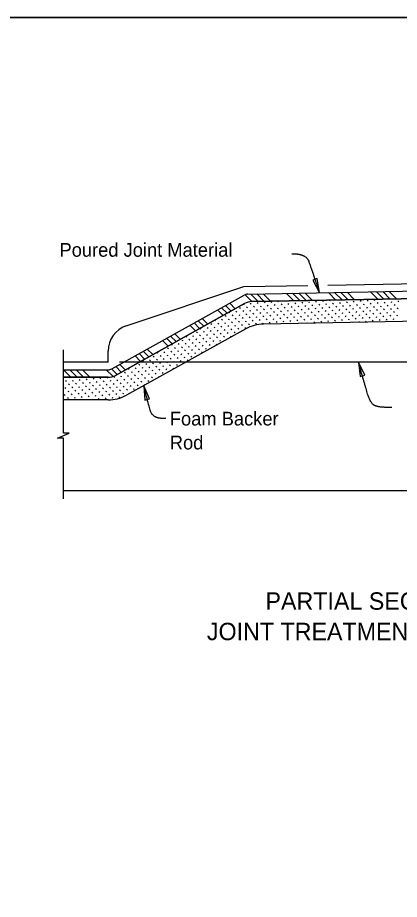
# Model space of a CAD drawing. Extents: x 0 to 15.4, y 0 to 9.7.
# Drawn here: x 5 to 7.109, y 4.865 to 9.73 of the extents above; entities that cross this region are included whole.
import ezdxf

# ---------------------------------------------------------------- set-up
doc = ezdxf.new("R2010")
doc.units = 0
for name, color, linetype in [('Dimension', 7, 'Continuous'), ('Miscellaneous', 7, 'Continuous'), ('Miscellaneous1', 7, 'Continuous'), ('SupstrConc', 7, 'Continuous'), ('SupstrConc_h', 7, 'Continuous'), ('TextStructures', 7, 'Continuous')]:
    doc.layers.add(name, color=color, linetype=linetype)

msp = doc.modelspace()

# ---------------------------------------------------------------- linework, layer by layer
at = {"layer": 'Dimension'}
for points in [[(6.6664, 8.2115), (6.6546, 8.2899), (6.6295, 8.2816)], [(6.8826, 7.8283), (6.8914, 7.7495), (6.9169, 7.7568)], [(5.6962, 7.6983), (5.7024, 7.6193), (5.7281, 7.6258)]]:
    msp.add_lwpolyline(points, close=True, dxfattribs=at)
msp.add_lwpolyline([(5.2525, 7.0744), (5.2525, 7.4095), (5.2194, 7.4095), (5.2834, 7.4378), (5.2525, 7.4378), (5.2525, 7.8962)], dxfattribs=at)
for points in [[(6.5146, 8.4272), (6.5542, 8.4272), (6.5971, 8.4085), (6.6125, 8.3755), (6.6664, 8.2115)], [(7.0668, 7.579), (6.995, 7.578), (6.9478, 7.6016), (6.9138, 7.7197), (6.8826, 7.8283)], [(5.8183, 7.5178), (5.7787, 7.5178), (5.7501, 7.5321), (5.7325, 7.5541), (5.6962, 7.6983)]]:
    msp.add_open_spline(points, degree=2, dxfattribs=at)
at = {"layer": 'Miscellaneous'}
for p, q in [((6.2709, 8.2042), (7.6932, 8.2305)), ((5.5197, 7.7924), (6.2514, 8.1989)), ((6.2563, 8.2002), (6.2936, 8.1629)), ((6.287, 8.2045), (6.328, 8.1635)), ((7.6925, 8.1888), (6.2925, 8.1629)), ((6.2925, 8.1629), (7.6925, 8.1888)), ((6.3214, 8.2051), (6.3623, 8.1642)), ((6.3558, 8.2058), (6.3967, 8.1648)), ((6.4845, 8.2081), (6.5255, 8.1672)), ((6.5189, 8.2088), (6.5598, 8.1678)), ((6.5532, 8.2094), (6.5942, 8.1685)), ((6.5876, 8.2101), (6.6285, 8.1691)), ((6.7164, 8.2124), (6.7573, 8.1715)), ((6.7507, 8.2131), (6.7917, 8.1721)), ((6.7851, 8.2137), (6.826, 8.1728)), ((6.8194, 8.2144), (6.8604, 8.1734)), ((6.9482, 8.2167), (6.9892, 8.1758)), ((6.9703, 8.1691), (6.9736, 8.1747)), ((6.9826, 8.2174), (7.0235, 8.1764)), ((7.0085, 8.1724), (7.0107, 8.1762)), ((7.0169, 8.218), (7.0579, 8.1771)), ((7.0467, 8.1756), (7.0474, 8.1769)), ((7.0513, 8.2186), (7.0922, 8.1777)), ((6.2535, 8.1524), (5.5399, 7.7559)), ((5.5399, 7.7559), (6.2535, 8.1524)), ((6.1261, 8.1293), (6.1567, 8.0986)), ((6.1486, 8.1418), (6.1792, 8.1111)), ((6.1711, 8.1543), (6.2017, 8.1236)), ((6.228, 8.125), (6.2312, 8.1306)), ((6.2487, 8.1457), (6.2519, 8.1513)), ((6.2661, 8.1283), (6.2694, 8.1339)), ((6.2868, 8.149), (6.2901, 8.1546)), ((6.3043, 8.1315), (6.3075, 8.1371)), ((6.325, 8.1522), (6.3282, 8.1578)), ((6.3424, 8.1347), (6.3457, 8.1403)), ((6.3631, 8.1554), (6.3664, 8.161)), ((6.3806, 8.138), (6.3838, 8.1436)), ((6.398, 8.1205), (6.4013, 8.1261)), ((6.4013, 8.1587), (6.4045, 8.1643)), ((6.4187, 8.1412), (6.422, 8.1468)), ((6.4362, 8.1238), (6.4394, 8.1294)), ((6.4394, 8.1619), (6.4416, 8.1656)), ((6.4569, 8.1445), (6.4601, 8.1501)), ((6.4743, 8.127), (6.4776, 8.1326)), ((6.4776, 8.1652), (6.4783, 8.1663)), ((6.495, 8.1477), (6.4983, 8.1533)), ((6.5125, 8.1303), (6.5157, 8.1359)), ((6.5332, 8.151), (6.5364, 8.1565)), ((6.5507, 8.1335), (6.5539, 8.1391)), ((6.5713, 8.1542), (6.5746, 8.1598)), ((6.5888, 8.1367), (6.592, 8.1423)), ((6.6063, 8.1193), (6.6095, 8.1249)), ((6.6095, 8.1574), (6.6127, 8.163)), ((6.627, 8.14), (6.6302, 8.1456)), ((6.6444, 8.1225), (6.6477, 8.1281)), ((6.6477, 8.1607), (6.6509, 8.1663)), ((6.6651, 8.1432), (6.6684, 8.1488)), ((6.6826, 8.1258), (6.6858, 8.1314)), ((6.6858, 8.1639), (6.6891, 8.1695)), ((6.7033, 8.1465), (6.7065, 8.1521)), ((6.7207, 8.129), (6.724, 8.1346)), ((6.724, 8.1672), (6.7261, 8.1709)), ((6.7414, 8.1497), (6.7447, 8.1553)), ((6.7589, 8.1322), (6.7621, 8.1378)), ((6.7621, 8.1704), (6.7628, 8.1716)), ((6.7796, 8.1529), (6.7828, 8.1585)), ((6.797, 8.1355), (6.8003, 8.1411)), ((6.8177, 8.1562), (6.821, 8.1618)), ((6.8352, 8.1387), (6.8384, 8.1443)), ((6.8526, 8.1213), (6.8559, 8.1269)), ((6.8559, 8.1594), (6.8591, 8.165)), ((6.8733, 8.142), (6.8766, 8.1476)), ((6.8908, 8.1245), (6.894, 8.1301)), ((6.894, 8.1627), (6.8973, 8.1683)), ((6.9115, 8.1452), (6.9147, 8.1508)), ((6.929, 8.1277), (6.9322, 8.1333)), ((6.9322, 8.1659), (6.9354, 8.1715)), ((6.9497, 8.1484), (6.9529, 8.154)), ((6.9671, 8.131), (6.9703, 8.1366)), ((6.9878, 8.1517), (6.991, 8.1573)), ((7.0053, 8.1342), (7.0085, 8.1398)), ((7.026, 8.1549), (7.0292, 8.1605)), ((7.0434, 8.1375), (7.0467, 8.1431)), ((7.0609, 8.12), (7.0641, 8.1256)), ((7.0641, 8.1582), (7.0674, 8.1638)), ((7.0816, 8.1407), (7.0848, 8.1463)), ((7.099, 8.1233), (7.1023, 8.1289)), ((7.1023, 8.1614), (7.1055, 8.167)), ((6.1036, 8.1168), (6.1342, 8.0861)), ((6.1484, 8.0804), (6.1517, 8.086)), ((6.1691, 8.1011), (6.1723, 8.1067)), ((6.1866, 8.0836), (6.1898, 8.0892)), ((6.2073, 8.1043), (6.2105, 8.1099)), ((6.2247, 8.0869), (6.228, 8.0925)), ((6.2454, 8.1076), (6.2487, 8.1132)), ((6.2629, 8.0901), (6.2661, 8.0957)), ((6.2803, 8.0727), (6.2836, 8.0783)), ((6.2836, 8.1108), (6.2868, 8.1164)), ((6.301, 8.0934), (6.3043, 8.099)), ((6.3185, 8.0759), (6.3217, 8.0815)), ((6.3217, 8.114), (6.325, 8.1196)), ((6.3392, 8.0966), (6.3424, 8.1022)), ((6.3566, 8.0791), (6.3599, 8.0847)), ((6.3599, 8.1173), (6.3631, 8.1229)), ((6.3773, 8.0998), (6.3806, 8.1054)), ((6.3948, 8.0824), (6.398, 8.088)), ((6.4155, 8.1031), (6.4187, 8.1087)), ((6.4329, 8.0856), (6.4362, 8.0912)), ((6.4536, 8.1063), (6.4569, 8.1119)), ((6.4711, 8.0889), (6.4743, 8.0945)), ((6.4886, 8.0714), (6.4918, 8.077)), ((6.4918, 8.1096), (6.495, 8.1152)), ((6.5093, 8.0921), (6.5125, 8.0977)), ((6.5267, 8.0746), (6.53, 8.0802)), ((6.53, 8.1128), (6.5332, 8.1184)), ((6.5474, 8.0953), (6.5507, 8.1009)), ((6.5649, 8.0779), (6.5681, 8.0835)), ((6.5681, 8.116), (6.5713, 8.1216)), ((6.5856, 8.0986), (6.5888, 8.1042)), ((6.603, 8.0811), (6.6063, 8.0867)), ((6.6237, 8.1018), (6.627, 8.1074)), ((6.6412, 8.0844), (6.6444, 8.09)), ((6.6619, 8.1051), (6.6651, 8.1107)), ((6.6793, 8.0876), (6.6826, 8.0932)), ((6.6968, 8.0702), (6.7, 8.0757)), ((6.7, 8.1083), (6.7033, 8.1139)), ((6.7175, 8.0908), (6.7207, 8.0964)), ((6.7349, 8.0734), (6.7382, 8.079)), ((6.7382, 8.1115), (6.7414, 8.1171)), ((6.7556, 8.0941), (6.7589, 8.0997)), ((6.7731, 8.0766), (6.7763, 8.0822)), ((6.7763, 8.1148), (6.7796, 8.1204)), ((6.7938, 8.0973), (6.797, 8.1029)), ((6.8112, 8.0799), (6.8145, 8.0855)), ((6.8145, 8.118), (6.8177, 8.1236)), ((6.8319, 8.1006), (6.8352, 8.1062)), ((6.8494, 8.0831), (6.8526, 8.0887)), ((6.8701, 8.1038), (6.8733, 8.1094)), ((6.8876, 8.0864), (6.8908, 8.092)), ((6.9083, 8.1071), (6.9115, 8.1127)), ((6.9257, 8.0896), (6.929, 8.0952)), ((6.9432, 8.0721), (6.9464, 8.0777)), ((6.9464, 8.1103), (6.9497, 8.1159)), ((6.9639, 8.0928), (6.9671, 8.0984)), ((6.9813, 8.0754), (6.9846, 8.081)), ((6.9846, 8.1135), (6.9878, 8.1191)), ((7.002, 8.0961), (7.0053, 8.1017)), ((7.0195, 8.0786), (7.0227, 8.0842)), ((7.0227, 8.1168), (7.026, 8.1224)), ((7.0402, 8.0993), (7.0434, 8.1049)), ((7.0576, 8.0819), (7.0609, 8.0875)), ((7.0783, 8.1026), (7.0816, 8.1082)), ((7.0958, 8.0851), (7.099, 8.0907)), ((5.9518, 8.0325), (5.9824, 8.0018)), ((5.9743, 8.045), (6.0049, 8.0143)), ((5.9968, 8.0575), (6.0274, 8.0268)), ((6.0193, 8.07), (6.0499, 8.0393)), ((6.0689, 8.0358), (6.0721, 8.0414)), ((6.0896, 8.0565), (6.0928, 8.062)), ((6.107, 8.039), (6.1103, 8.0446)), ((6.1245, 8.0215), (6.1277, 8.0271)), ((6.1277, 8.0597), (6.131, 8.0653)), ((6.1452, 8.0422), (6.1484, 8.0478)), ((6.1626, 8.0248), (6.1659, 8.0304)), ((6.1659, 8.0629), (6.1691, 8.0685)), ((6.1833, 8.0455), (6.1866, 8.0511)), ((6.2008, 8.028), (6.204, 8.0336)), ((6.204, 8.0662), (6.2073, 8.0718)), ((6.2215, 8.0487), (6.2247, 8.0543)), ((6.2389, 8.0313), (6.2422, 8.0369)), ((6.2422, 8.0694), (6.2454, 8.075)), ((6.2596, 8.052), (6.2629, 8.0576)), ((6.2771, 8.0345), (6.2803, 8.0401)), ((6.2978, 8.0552), (6.301, 8.0608)), ((6.3152, 8.0377), (6.3185, 8.0433)), ((6.3359, 8.0584), (6.3392, 8.064)), ((6.3534, 8.041), (6.3566, 8.0466)), ((7.6901, 8.0638), (6.3571, 8.0391)), ((6.3741, 8.0617), (6.3773, 8.0673)), ((6.3916, 8.0442), (6.3948, 8.0498)), ((6.4122, 8.0649), (6.4155, 8.0705)), ((6.4297, 8.0475), (6.4329, 8.0531)), ((6.4504, 8.0682), (6.4536, 8.0738)), ((6.4679, 8.0507), (6.4711, 8.0563)), ((6.506, 8.0539), (6.5093, 8.0595)), ((6.5442, 8.0572), (6.5474, 8.0628)), ((6.5635, 8.0429), (6.5649, 8.0453)), ((6.5823, 8.0604), (6.5856, 8.066)), ((6.6001, 8.0436), (6.603, 8.0486)), ((6.6205, 8.0637), (6.6237, 8.0693)), ((6.6379, 8.0462), (6.6412, 8.0518)), ((6.6586, 8.0669), (6.6619, 8.0725)), ((6.6761, 8.0495), (6.6793, 8.0551)), ((6.7142, 8.0527), (6.7175, 8.0583)), ((6.7524, 8.0559), (6.7556, 8.0615)), ((6.7906, 8.0592), (6.7938, 8.0648)), ((6.8287, 8.0624), (6.8319, 8.068)), ((6.848, 8.0482), (6.8494, 8.0506)), ((6.8669, 8.0657), (6.8701, 8.0713)), ((6.8847, 8.0488), (6.8876, 8.0538)), ((6.905, 8.0689), (6.9083, 8.0745)), ((6.9225, 8.0514), (6.9257, 8.057)), ((6.9606, 8.0547), (6.9639, 8.0603)), ((6.9988, 8.0579), (7.002, 8.0635)), ((7.0369, 8.0612), (7.0402, 8.0668)), ((7.0751, 8.0644), (7.0783, 8.07)), ((6.2598, 8.0129), (5.6006, 7.6466)), ((5.8675, 7.9856), (5.8981, 7.9549)), ((5.9893, 7.9911), (5.9926, 7.9967)), ((6.0068, 7.9737), (6.01, 7.9793)), ((6.01, 8.0118), (6.0133, 8.0174)), ((6.0275, 7.9944), (6.0307, 8)), ((6.0449, 7.9769), (6.0482, 7.9825)), ((6.0482, 8.0151), (6.0514, 8.0207)), ((6.0656, 7.9976), (6.0689, 8.0032)), ((6.0831, 7.9801), (6.0863, 7.9857)), ((6.0863, 8.0183), (6.0896, 8.0239)), ((6.1038, 8.0008), (6.107, 8.0064)), ((6.1212, 7.9834), (6.1245, 7.989)), ((6.1419, 8.0041), (6.1452, 8.0097)), ((6.1594, 7.9866), (6.1626, 7.9922)), ((6.1801, 8.0073), (6.1833, 8.0129)), ((6.1975, 7.9899), (6.2008, 7.9955)), ((6.2182, 8.0106), (6.2215, 8.0162)), ((6.2564, 8.0138), (6.2596, 8.0194)), ((5.8, 7.9481), (5.8306, 7.9174)), ((5.8225, 7.9606), (5.8531, 7.9299)), ((5.845, 7.9731), (5.8756, 7.9424)), ((5.8891, 7.9258), (5.8923, 7.9314)), ((5.9098, 7.9465), (5.913, 7.9521)), ((5.9272, 7.929), (5.9305, 7.9346)), ((5.9305, 7.9672), (5.9337, 7.9728)), ((5.9479, 7.9497), (5.9512, 7.9553)), ((5.9654, 7.9323), (5.9686, 7.9379)), ((5.9686, 7.9704), (5.9719, 7.976)), ((5.9861, 7.953), (5.9893, 7.9586)), ((6.0035, 7.9355), (6.0068, 7.9411)), ((6.0242, 7.9562), (6.0275, 7.9618)), ((6.0417, 7.9387), (6.0449, 7.9443)), ((6.0624, 7.9594), (6.0656, 7.965)), ((6.0798, 7.942), (6.0831, 7.9476)), ((6.0973, 7.9245), (6.1005, 7.9301)), ((6.1005, 7.9627), (6.1038, 7.9683)), ((6.118, 7.9452), (6.1212, 7.9508)), ((6.1387, 7.9659), (6.1419, 7.9715)), ((6.1768, 7.9692), (6.1801, 7.9748)), ((5.6932, 7.8888), (5.7238, 7.8581)), ((5.7157, 7.9013), (5.7463, 7.8706)), ((5.7714, 7.8779), (5.7746, 7.8835)), ((5.8095, 7.8811), (5.8128, 7.8867)), ((5.8302, 7.9018), (5.8335, 7.9074)), ((5.8477, 7.8844), (5.8509, 7.89)), ((5.8509, 7.9225), (5.8542, 7.9281)), ((5.8684, 7.9051), (5.8716, 7.9107)), ((5.8858, 7.8876), (5.8891, 7.8932)), ((5.9065, 7.9083), (5.9098, 7.9139)), ((5.924, 7.8909), (5.9272, 7.8965)), ((5.9447, 7.9116), (5.9479, 7.9172)), ((5.9621, 7.8941), (5.9654, 7.8997)), ((5.9796, 7.8767), (5.9828, 7.8823)), ((5.9828, 7.9148), (5.9861, 7.9204)), ((6.0003, 7.8974), (6.0035, 7.9029)), ((6.0177, 7.8799), (6.021, 7.8855)), ((6.021, 7.918), (6.0242, 7.9236)), ((6.0384, 7.9006), (6.0417, 7.9062)), ((6.0591, 7.9213), (6.0624, 7.9269)), ((5.6482, 7.8638), (5.6788, 7.8331)), ((5.6707, 7.8763), (5.7013, 7.8456)), ((5.6918, 7.8333), (5.6951, 7.8389)), ((5.73, 7.8365), (5.7332, 7.8421)), ((5.7507, 7.8572), (5.7539, 7.8628)), ((5.7681, 7.8398), (5.7714, 7.8453)), ((5.7888, 7.8604), (5.7921, 7.866)), ((5.8063, 7.843), (5.8095, 7.8486)), ((5.827, 7.8637), (5.8302, 7.8693)), ((5.8444, 7.8462), (5.8477, 7.8518)), ((5.8619, 7.8288), (5.8651, 7.8344)), ((5.8651, 7.8669), (5.8684, 7.8725)), ((5.8826, 7.8495), (5.8858, 7.8551)), ((5.9, 7.832), (5.9033, 7.8376)), ((5.9033, 7.8702), (5.9065, 7.8758)), ((5.9207, 7.8527), (5.924, 7.8583)), ((5.9382, 7.8353), (5.9414, 7.8409)), ((5.9414, 7.8734), (5.9447, 7.879)), ((5.9589, 7.856), (5.9621, 7.8616)), ((5.2525, 7.7454), (5.2525, 7.7871)), ((5.2525, 7.7871), (5.4994, 7.7871)), ((5.2525, 7.7871), (5.2942, 7.7454)), ((5.2875, 7.7871), (5.3292, 7.7454)), ((5.3225, 7.7871), (5.3642, 7.7454)), ((5.3575, 7.7871), (5.3992, 7.7454)), ((5.4887, 7.7871), (5.5247, 7.7511)), ((5.5187, 7.7921), (5.5495, 7.7613)), ((5.5414, 7.8044), (5.572, 7.7738)), ((5.5639, 7.8169), (5.5945, 7.7863)), ((5.6123, 7.7886), (5.6155, 7.7942)), ((5.6504, 7.7919), (5.6537, 7.7975)), ((5.6711, 7.8126), (5.6744, 7.8182)), ((5.6886, 7.7951), (5.6918, 7.8007)), ((5.7093, 7.8158), (5.7125, 7.8214)), ((5.7267, 7.7984), (5.73, 7.804)), ((5.7442, 7.7809), (5.7474, 7.7865)), ((5.7474, 7.8191), (5.7507, 7.8247)), ((5.7649, 7.8016), (5.7681, 7.8072)), ((5.7823, 7.7841), (5.7856, 7.7897)), ((5.7856, 7.8223), (5.7888, 7.8279)), ((5.803, 7.8048), (5.8063, 7.8104)), ((5.8205, 7.7874), (5.8237, 7.793)), ((5.8237, 7.8255), (5.827, 7.8311)), ((5.8412, 7.8081), (5.8444, 7.8137)), ((5.8586, 7.7906), (5.8619, 7.7962)), ((5.8793, 7.8113), (5.8826, 7.8169)), ((5.4994, 7.7454), (5.2525, 7.7454)), ((5.2525, 7.6204), (5.2525, 7.7454)), ((5.2525, 7.7454), (5.4994, 7.7454)), ((5.2863, 7.742), (5.2883, 7.7454)), ((5.3245, 7.7452), (5.3246, 7.7454)), ((5.3801, 7.731), (5.3833, 7.7366)), ((5.4182, 7.7343), (5.4215, 7.7399)), ((5.4564, 7.7375), (5.4596, 7.7431)), ((5.4946, 7.7408), (5.4973, 7.7454)), ((5.5327, 7.744), (5.536, 7.7496)), ((5.5709, 7.7472), (5.5741, 7.7528)), ((5.5883, 7.7298), (5.5916, 7.7354)), ((5.5916, 7.7679), (5.5948, 7.7735)), ((5.609, 7.7505), (5.6123, 7.7561)), ((5.6265, 7.733), (5.6297, 7.7386)), ((5.6297, 7.7712), (5.633, 7.7768)), ((5.6472, 7.7537), (5.6504, 7.7593)), ((5.6646, 7.7363), (5.6679, 7.7419)), ((5.6679, 7.7744), (5.6711, 7.78)), ((5.6853, 7.757), (5.6886, 7.7626)), ((5.7028, 7.7395), (5.706, 7.7451)), ((5.706, 7.7777), (5.7093, 7.7833)), ((5.7235, 7.7602), (5.7267, 7.7658)), ((5.7409, 7.7427), (5.7442, 7.7483)), ((5.7616, 7.7634), (5.7649, 7.769)), ((5.7791, 7.746), (5.7823, 7.7516)), ((5.7998, 7.7667), (5.803, 7.7723)), ((5.2624, 7.6832), (5.2656, 7.6888)), ((5.2656, 7.7213), (5.2689, 7.7269)), ((5.2831, 7.7039), (5.2863, 7.7095)), ((5.3005, 7.6864), (5.3038, 7.692)), ((5.3038, 7.7246), (5.307, 7.7301)), ((5.3212, 7.7071), (5.3245, 7.7127)), ((5.3387, 7.6896), (5.3419, 7.6952)), ((5.3419, 7.7278), (5.3452, 7.7334)), ((5.3594, 7.7103), (5.3626, 7.7159)), ((5.3769, 7.6929), (5.3801, 7.6985)), ((5.3976, 7.7136), (5.4008, 7.7192)), ((5.415, 7.6961), (5.4182, 7.7017)), ((5.4357, 7.7168), (5.4389, 7.7224)), ((5.4532, 7.6994), (5.4564, 7.705)), ((5.4706, 7.6819), (5.4739, 7.6875)), ((5.4739, 7.7201), (5.4771, 7.7257)), ((5.4913, 7.7026), (5.4946, 7.7082)), ((5.5088, 7.6851), (5.512, 7.6907)), ((5.512, 7.7233), (5.5153, 7.7289)), ((5.5295, 7.7058), (5.5327, 7.7114)), ((5.5469, 7.6884), (5.5502, 7.694)), ((5.5502, 7.7265), (5.5534, 7.7321)), ((5.5676, 7.7091), (5.5709, 7.7147)), ((5.5851, 7.6916), (5.5883, 7.6972)), ((5.6058, 7.7123), (5.609, 7.7179)), ((5.6232, 7.6949), (5.6265, 7.7005)), ((5.6439, 7.7156), (5.6472, 7.7212)), ((5.6614, 7.6981), (5.6646, 7.7037)), ((5.6821, 7.7188), (5.6853, 7.7244)), ((5.6998, 7.7017), (5.7028, 7.7069)), ((5.7202, 7.722), (5.7235, 7.7276)), ((5.2592, 7.645), (5.2624, 7.6506)), ((5.2798, 7.6657), (5.2831, 7.6713)), ((5.2973, 7.6482), (5.3005, 7.6538)), ((5.318, 7.6689), (5.3212, 7.6745)), ((5.3355, 7.6515), (5.3387, 7.6571)), ((5.3529, 7.634), (5.3562, 7.6396)), ((5.3562, 7.6722), (5.3594, 7.6778)), ((5.3736, 7.6547), (5.3769, 7.6603)), ((5.3911, 7.6373), (5.3943, 7.6429)), ((5.3943, 7.6754), (5.3976, 7.681)), ((5.4118, 7.658), (5.415, 7.6636)), ((5.4292, 7.6405), (5.4325, 7.6461)), ((5.4325, 7.6787), (5.4357, 7.6843)), ((5.4499, 7.6612), (5.4532, 7.6668)), ((5.4674, 7.6438), (5.4706, 7.6493)), ((5.4881, 7.6644), (5.4913, 7.67)), ((5.5055, 7.647), (5.5088, 7.6526)), ((5.5262, 7.6677), (5.5295, 7.6733)), ((5.5437, 7.6502), (5.5469, 7.6558)), ((5.5611, 7.6328), (5.5644, 7.6384)), ((5.5644, 7.6709), (5.5676, 7.6765)), ((5.5818, 7.6535), (5.5851, 7.6591)), ((5.6025, 7.6742), (5.6058, 7.6798)), ((5.6206, 7.6578), (5.6232, 7.6623)), ((5.6407, 7.6774), (5.6439, 7.683)), ((5.4994, 7.6204), (5.2525, 7.6204)), ((5.2766, 7.6275), (5.2798, 7.6331)), ((5.3148, 7.6308), (5.318, 7.6364)), ((5.3726, 7.6204), (5.3736, 7.6222)), ((5.4089, 7.6204), (5.4118, 7.6254)), ((5.4467, 7.6231), (5.4499, 7.6287)), ((5.4848, 7.6263), (5.4881, 7.6319)), ((5.523, 7.6295), (5.5262, 7.6351))]:
    msp.add_line(p, q, dxfattribs=at)
msp.add_lwpolyline([(0, 0), (15.394, 0), (15.394, 9.7298), (0, 9.7298)], close=True, dxfattribs=at)
for centre, radius, start, end in [((6.2717, 8.1625), 0.0417, 91.0616, 119.0562), ((6.294, 8.0796), 0.0833, 91.0616, 119.0562), ((6.294, 8.0796), 0.0833, 91.0616, 119.0562), ((6.3609, 7.8308), 0.2083, 91.0616, 119.0562), ((5.4994, 7.8288), 0.0417, 269.9997, 299.0562), ((5.4994, 7.8287), 0.0833, 269.9997, 299.0562), ((5.4994, 7.8287), 0.0833, 269.9997, 299.0562), ((5.4994, 7.8287), 0.2083, 269.9997, 299.0562)]:
    msp.add_arc(centre, radius, start, end, dxfattribs=at)
at = {"layer": 'Miscellaneous1'}
msp.add_lwpolyline([(0, 9.7298), (15.394, 9.7298), (15.394, 0), (0, 0)], close=True, dxfattribs=at)
at = {"layer": 'SupstrConc'}
for p, q in [((6.7133, 8.2541), (7.694, 8.2723)), ((5.599, 8.0287), (6.2493, 8.2455)), ((6.2494, 8.2455), (6.6034, 8.2521)), ((5.4993, 7.8287), (5.4993, 7.8904)), ((5.2525, 7.1204), (10.1384, 7.1204))]:
    msp.add_line(p, q, dxfattribs=at)
msp.add_lwpolyline([(5.4994, 7.8288), (5.2525, 7.8288)], dxfattribs=at)
msp.add_arc((5.6452, 7.8904), 0.1458, 108.4349, 180, dxfattribs=at)
at = {"layer": 'SupstrConc_h'}
msp.add_lwpolyline([(9.1761, 7.8288), (5.5626, 7.8288)], dxfattribs=at)

# ---------------------------------------------------------------- texts
at = {"layer": 'Dimension'}
for s, height, p in [('Foam Backer ', 0.0756, (5.8403, 7.4795)), ('Rod', 0.0756, (5.8403, 7.3475)), ('PARTIAL SECTION ALONG ℄ JOINT,', 0.096, (6.3689, 6.4629)), ('JOINT TREATMENT AT TRAFFIC SEPARATOR', 0.096, (6.0453, 6.2949))]:
    msp.add_text(s, height=height, dxfattribs=at).set_placement(p)
at = {"layer": 'TextStructures'}
msp.add_text('Poured Joint Material', height=0.0756, dxfattribs=at).set_placement((5.2308, 8.4106))

doc.saveas('drawing.dxf')
